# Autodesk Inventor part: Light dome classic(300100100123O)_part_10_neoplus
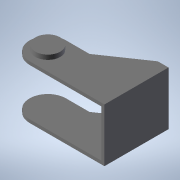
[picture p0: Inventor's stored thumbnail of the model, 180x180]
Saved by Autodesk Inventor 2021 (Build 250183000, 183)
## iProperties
Created: 2026-04
Part Number: Light dome classic(300100100123O)_part_10_neoplus
Material: Generic
Catalog Web Link: www.3dfindit.com
Description: Light dome classic_part_10_neoplus-
Vendor: KINGSPAN
Document SubType Name: Modeling
Designer: psAdmin
Manufacturer: KINGSPAN
Mass: 33.5145 g
Surface Area: 225.296 cm^2
Volume: 33.5145 cm^3
Density: 1 g/cm^3
Appearance: PSOLRGB-255-255-255
Category: PARTsolutions
Company: KINGSPAN
Title: Light dome classic(300100100123O)_part_10_neoplus
Author: Cadenas PARTsolutions
PSOL_IDENT_0: {$CADENAS_DATA/23d-libs/kingspan_kla/light_dome_classic_neoplus/parts/part_10.prj},291 {VTYP=3D},{NB=
PSOL_IDENT_1: Light dome classic(300100100123O)_part_10_neoplus},{LINA=Light dome classic(300100100123O)_part_10_n
PSOL_IDENT_2: eoplus},{NN=Light dome classic_part_10_neoplus},{DATE=15.07.2024 10:56:16},{GEOMDATE=01.07.2024 07:0
PSOL_IDENT_3: 4:16},{VERSION=},{LINEID=10},{WBVAR=LODLEVEL,L,W,DP,OP,BA,OC},{WBNUMERIC=W}  {NB=Light dome classic(
PSOL_IDENT_4: 300100100123O)_part_10_neoplus},{LINA=Light dome classic(300100100123O)_part_10_neoplus},{KT=DUMMY},
PSOL_IDENT_5: {IDNR=},{PN=Light dome classic},{LODLEVEL=300},{L=100},{W=100},{DRIVE=1},{WX=100,150,200,250,300},{D
PSOL_IDENT_6: P=1},{OP=2},{BA=3},{OC=O},{OPX='1','manualy','2','Linear drive 300 mm stroke 24 V and 230 V','3','Li
PSOL_IDENT_7: near drive 500 mm stroke 24 V and 230 V','4','Linear drive 750 mm stroke 24 V and 230 V'},{LX=1000},
PSOL_IDENT_8: {XWX=1000},{HEI=1048.274},{VER=1},{DPX='3', 'Fixed','1', 'Natural ventilation' ,'4','NSHE', '2', 'NS
PSOL_IDENT_9: HEV'}
NB: Light dome classic(300100100123O)_part_10_neoplus
NN: Light dome classic_part_10_neoplus
NBSYN: $PN.($LODLEVEL.$L.$W.$DP.$OP.$BA.$OC.)_part_10_neoplus
LINA: Light dome classic(300100100123O)_part_10_neoplus
CATALOG: Light + Air
PN: Light dome classic
LODLEVEL: 300
L: 100
W: 100
DP: Natural ventilation
OP: Linear drive 300 mm stroke 24 V and 230 V
BA: PVC base 50 cm
OC: Open
SUPPLIER: KINGSPAN
ARTICLENO: Light dome classic(300100100123O)_part_10_neoplus
BOMINFO: Light dome classic(300100100123O)_part_10_neoplus
CREATOR: CADENAS GmbH
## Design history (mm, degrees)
sketch "Sketch_1"
  geometry: L1 (-17, 22)-(67, 22); L2 (67, 22)-(67, -22); L3 (67, -22)-(-17, -22); L4 (-17, -22)-(-17, -25); L5 (-17, -25)-(70, -25); L6 (70, -25)-(70, 25); L7 (70, 25)-(-17, 25); L8 (-17, 25)-(-17, 22)
  constraints: 16 end point
extrude "Extrusion1" join sketch "Sketch_1" distance "d0" = 63; taper "d1" = 0 deg
sketch "Sketch_2"
  geometry: L1 (27, -53)-(27, 27); L2 (27, 27)-(-80, 27); L3 (-80, 27)-(-80, -53); L4 (-80, -53)-(27, -53); L5 (0, 17)-(-70, 17); L6 (-70, 17)-(-70, -43); L7 (-70, -43)-(-60, -43); L8 (-60, -43)-(-22, -17); L9 (-22, -17)-(0, -17); A1 r 17 centre (0, 0) between (0, -17) and (0, 17)
  constraints: 18 end point, 2 point on circle, 1 centre point
extrude "Extrusion2" cut sketch "Sketch_2" stored distance "d2" = 100; taper "d3" = 0 deg
sketch "Sketch_3"
  geometry: L1 (0, 22.02)-(0, 30.12); L2 (0, 30.12)-(11.65, 30.12); L3 (11.65, 30.12)-(11.65, 25.85); L4 (11.65, 25.85)-(8.925, 25.85); L5 (8.925, 25.85)-(8.925, 22.02); L6 (8.925, 22.02)-(0, 22.02); L7 (0, 22.02)-(0, 30.12)
  constraints: 14 end point
revolve "Revolution1" sketch "Sketch_3" stored, may be unused: angle "d4" = 360 deg
sketch "Sketch_5"
  geometry: L1 (0, -30.12)-(0, -22.02); L2 (0, -22.02)-(8.925, -22.02); L3 (8.925, -22.02)-(8.925, -25.85); L4 (8.925, -25.85)-(11.65, -25.85); L5 (11.65, -25.85)-(11.65, -30.12); L6 (11.65, -30.12)-(0, -30.12); L7 (0, -30.12)-(0, -22.02)
  constraints: 14 end point
revolve "Revolution2" sketch "Sketch_5" stored, may be unused: angle "d5" = 360 deg
node "IP_10_XY"
node "IP_10_YZ"
node "IP_10_ZX"
node "IP_10_X"
node "IP_10_Y"
node "IP_10_Z"
node "IP_10_Center"
node "IP_for_part_7_XY"
node "IP_for_part_7_YZ"
node "IP_for_part_7_ZX"
node "IP_for_part_7_X"
node "IP_for_part_7_Y"
node "IP_for_part_7_Z"
node "IP_for_part_7_Center"
body "Solid1"
